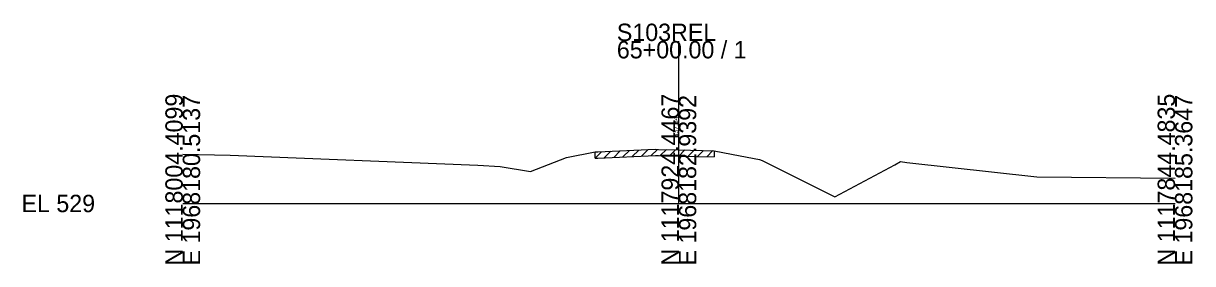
# Model space of a CAD drawing. Extents: x -26 to 163, y -10 to 24518.
# Drawn here: x -25.7 to 162.8, y 13490.3 to 13529 of the extents above; entities that cross this region are included whole.
import ezdxf

# ---------------------------------------------------------------- set-up
doc = ezdxf.new("R2010")
doc.units = 0
for name, color, linetype in [('RD_GPK_XS_Cell', 7, 'Continuous'), ('RD_XS_ExGround', 7, 'Continuous'), ('RD_XS_ExPaveRet', 7, 'Continuous'), ('RD_XS_TX_Elev_EX', 7, 'Continuous')]:
    doc.layers.add(name, color=color, linetype=linetype)

msp = doc.modelspace()

# ---------------------------------------------------------------- linework, layer by layer
at = {"layer": 'RD_GPK_XS_Cell'}
for p, q in [((80, 13500), (80, 13526.18)), ((0, 13500), (80, 13500)), ((80, 13500), (160, 13500))]:
    msp.add_line(p, q, dxfattribs=at)
at = {"layer": 'RD_XS_ExGround'}
msp.add_lwpolyline([(0, 13507.96), (7.66, 13507.79), (47.56, 13506.15), (51.17, 13505.98), (56.06, 13505.16), (61.87, 13507.4), (66.48, 13508.3), (66.93, 13508.32), (76.24, 13508.73), (76.73, 13508.72), (80, 13508.64), (85.71, 13508.5), (89.89, 13507.7), (93, 13507.09), (93.41, 13506.91), (105.17, 13501.08), (114.83, 13506.25), (115.76, 13506.77), (116.78, 13506.6), (137.7, 13504.3), (160, 13504.08)], dxfattribs=at)
at = {"layer": 'RD_XS_ExPaveRet'}
for p, q in [((67.98, 13507.36), (69.03, 13508.41)), ((69.49, 13507.43), (70.53, 13508.47)), ((70.99, 13507.49), (72.04, 13508.54)), ((72.49, 13507.56), (73.54, 13508.61)), ((73.99, 13507.63), (75.04, 13508.67)), ((75.5, 13507.69), (76.53, 13508.72)), ((77, 13507.71), (77.98, 13508.69)), ((78.5, 13507.68), (79.48, 13508.65)), ((80, 13507.64), (80.98, 13508.62)), ((81.5, 13507.6), (82.48, 13508.58)), ((83.01, 13507.57), (83.98, 13508.54)), ((84.51, 13507.53), (85.49, 13508.51)), ((85.71, 13508.5), (85.71, 13507.5)), ((66.48, 13507.3), (67.53, 13508.34)), ((66.48, 13507.3), (66.48, 13508.3)), ((66.48, 13507.3), (66.93, 13507.32)), ((66.93, 13507.32), (76.24, 13507.73)), ((76.24, 13507.73), (76.73, 13507.72)), ((76.73, 13507.72), (80, 13507.64)), ((80, 13507.64), (85.71, 13507.5))]:
    msp.add_line(p, q, dxfattribs=at)

# ---------------------------------------------------------------- texts
at = {"layer": 'RD_GPK_XS_Cell'}
for s, p in [('S103REL', (70, 13526.18)), ('65+00.00 / 1', (70, 13523.38)), ('EL 529', (-26, 13498.6))]:
    msp.add_text(s, height=2.8, dxfattribs=at).set_placement(p)
for s, p in [('N 1118004.4099', (0, 13490)), ('E 1968180.5137', (2.8, 13490)), ('N 1117924.4467', (80, 13490)), ('E 1968182.9392', (82.8, 13490)), ('N 1117844.4835', (160, 13490)), ('E 1968185.3647', (162.8, 13490))]:
    msp.add_text(s, height=2.8, rotation=90, dxfattribs=at).set_placement(p)
at = {"layer": 'RD_XS_TX_Elev_EX'}
msp.add_text('537.64', height=0.8, rotation=90, dxfattribs=at).set_placement((79.9, 13510.64))

doc.saveas('drawing.dxf')
